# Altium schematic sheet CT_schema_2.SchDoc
size 591 x 347 mm
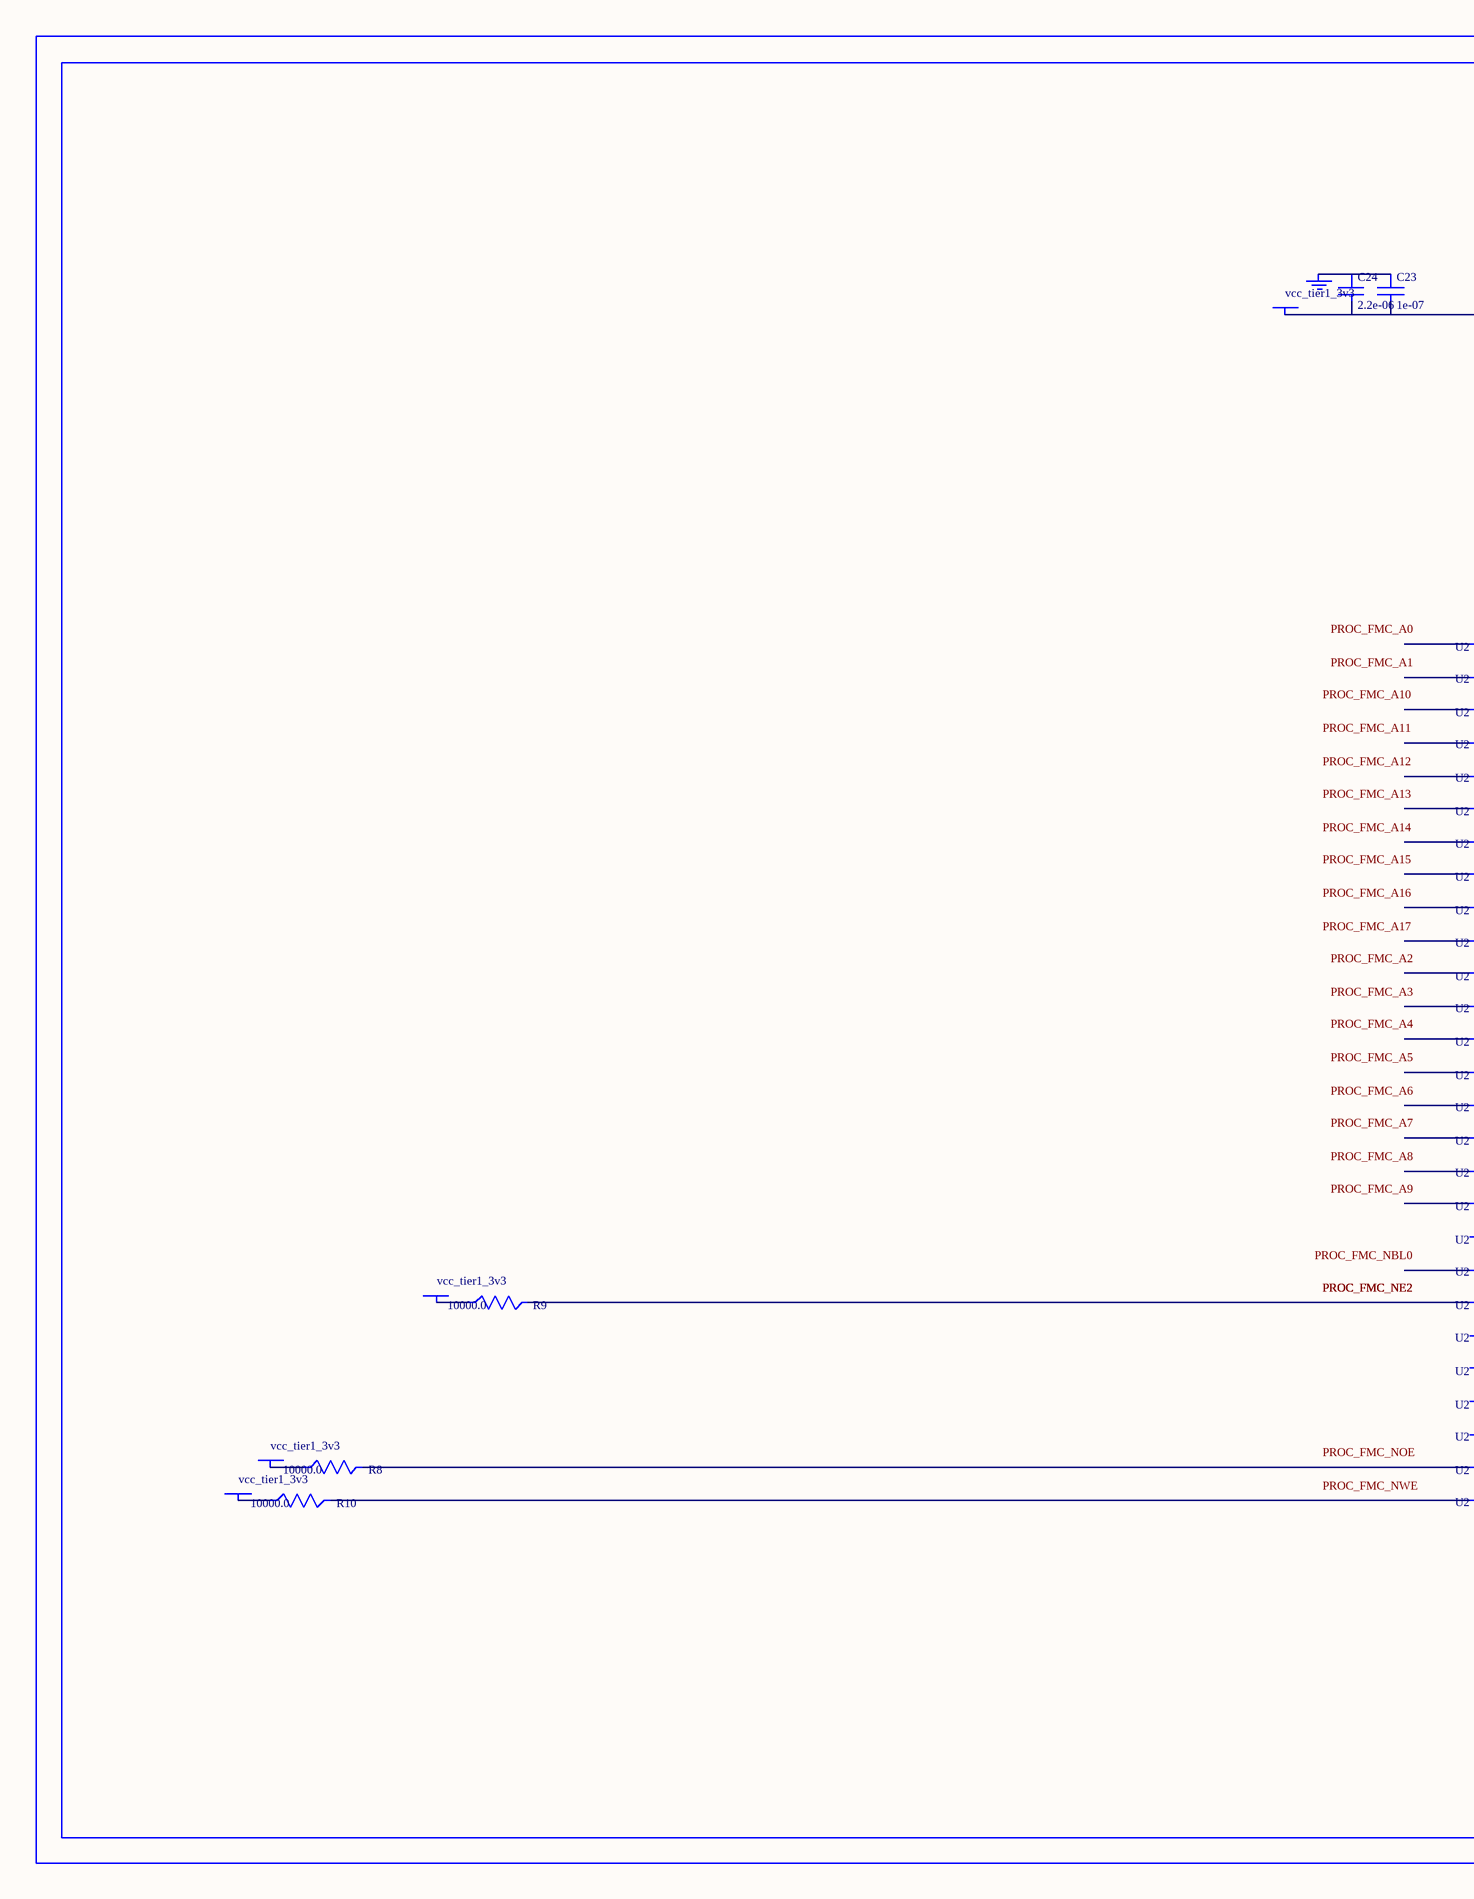
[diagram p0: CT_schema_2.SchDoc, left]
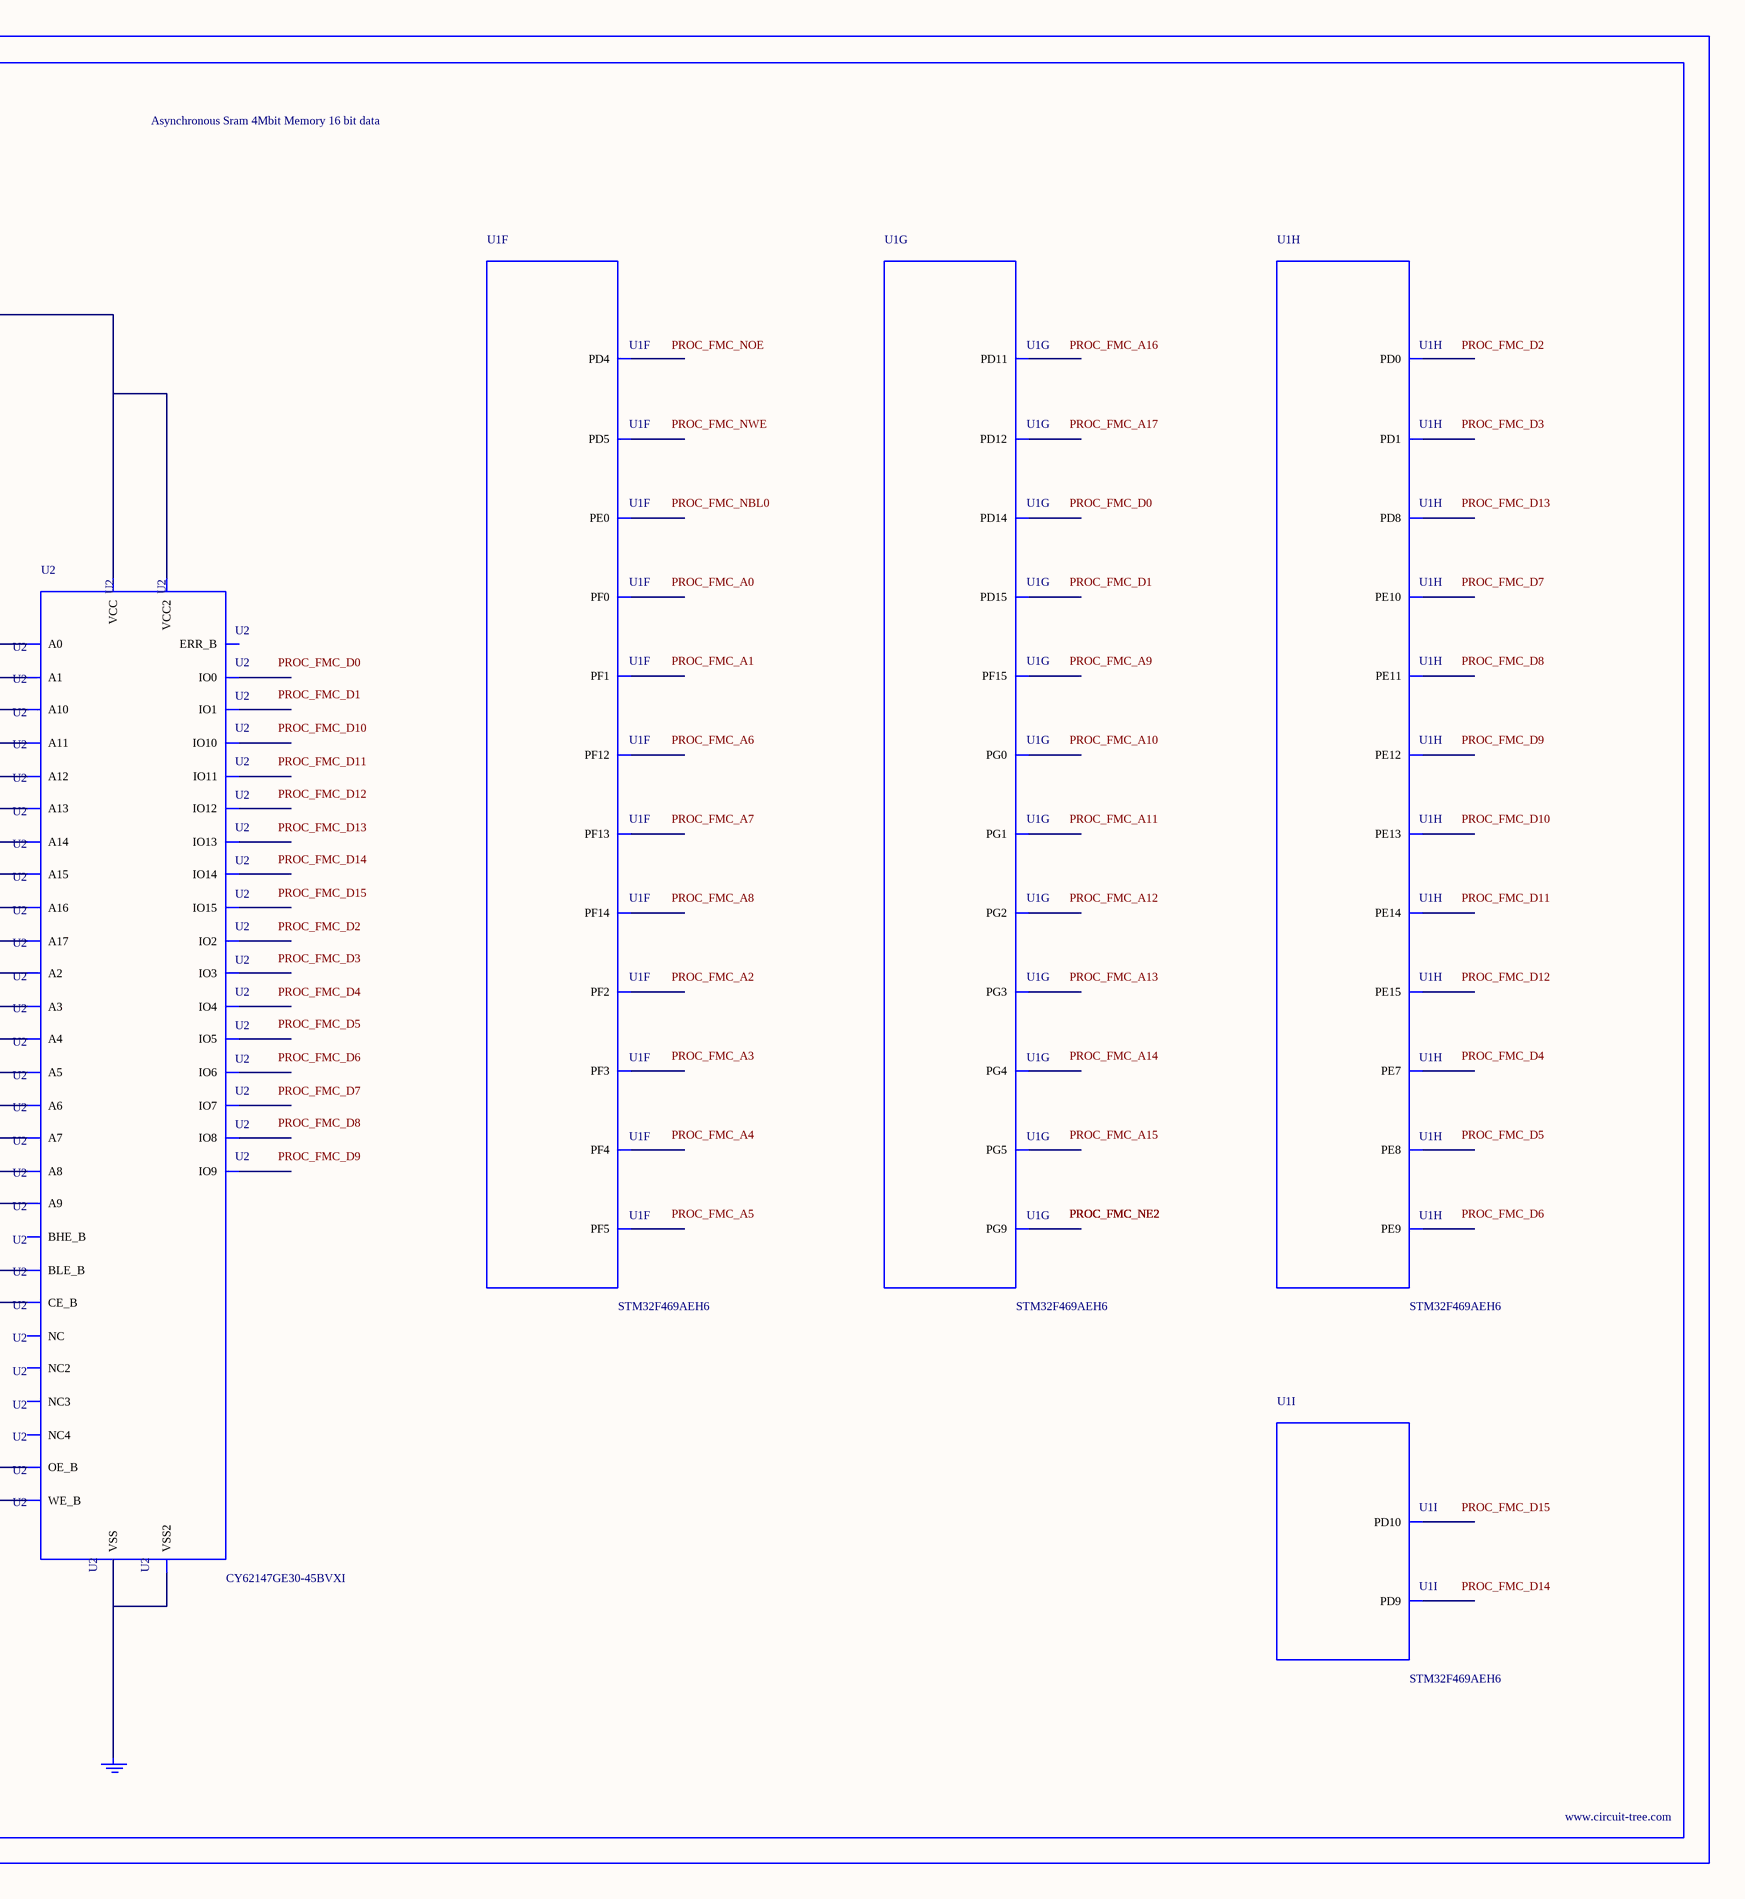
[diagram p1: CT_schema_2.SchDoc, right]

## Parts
BORDER1  (no value)
C23  1e-07  [C0402]
C24  2.2e-06  [C0603]
GND_INSTANCE_1_0  (no value)
GND_INSTANCE_1_1  (no value)
POWER_INSTANCE_1_0  vcc_tier1_3v3
POWER_INSTANCE_1_1  vcc_tier1_3v3
POWER_INSTANCE_1_2  vcc_tier1_3v3
POWER_INSTANCE_1_3  vcc_tier1_3v3
R8  10000.0  [R0603]
R9  10000.0  [R0603]
R10  10000.0  [R0603]
U1  STM32F469AEH6  [UFBGA169]  (parts F,G,H,I of 14)
U2  CY62147GE30-45BVXI  [VFBGA48]

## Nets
NetC23_1: C23.1 C24.1 GND_INSTANCE_1_0.0(GND)
NetC23_2: C23.2 C24.2 POWER_INSTANCE_1_0.0(PWR) U2.D6(VCC) U2.E1(VCC2)
NetGND_INSTANCE_1_1_0: GND_INSTANCE_1_1.0(GND) U2.D1(VSS) U2.E6(VSS2)
NetPOWER_INSTANCE_1_1_0: POWER_INSTANCE_1_1.0(PWR) R8.1
NetPOWER_INSTANCE_1_2_0: POWER_INSTANCE_1_2.0(PWR) R9.1
NetPOWER_INSTANCE_1_3_0: POWER_INSTANCE_1_3.0(PWR) R10.1
NetR8_2: R8.2 U2.A2(OE_B)
NetR9_2: R9.2 U2.B5(CE_B)
NetR10_2: R10.2 U2.G5(WE_B)

Not connected (* = marked no-connect by the designer): U1 A4(PE0) B7(PD5) C6(PD4) C7(PD1) C9(PD0) E6(PG9) E12(PG5) E13(PG4) F3(PF0) F12(PG3) F13(PG2) G3(PF1) G5(PF2) G6(PE8) H3(PF5) H4(PF3) H5(PF14) H6(PE9) H7(PE10) J8(PE13) K7(PE11) K8(PE14) L4(PF4) L7(PE12) L8(PE15) L10(PD8) L11(PD10) L12(PD14) L13(PD15) M4(PF13) M6(PF15) M7(PG1) M10(PD9) M11(PD11) M13(PD12) N5(PF12) N6(PG0) N7(PE7); U2 A1(BLE_B) A3(A0) A4(A1) A5(A2) A6(NC) B1(IO8) B2(BHE_B) B3(A3) B4(A4) B6(IO0) C1(IO9) C2(IO10) C3(A5) C4(A6) C5(IO1) C6(IO2) D2(IO11) D3(A17) D4(A7) D5(IO3) E2(IO12) E3(ERR_B) E4(A16) E5(IO4) F1(IO14) F2(IO13) F3(A14) F4(A15) F5(IO5) F6(IO6) G1(IO15) G2(NC2) G3(A12) G4(A13) G6(IO7) H1(NC3) H2(A8) H3(A9) H4(A10) H5(A11) H6(NC4)

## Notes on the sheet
- Labels drawn without touching a wire or pin: PROC_FMC_A0, PROC_FMC_A1, PROC_FMC_A2, PROC_FMC_A3, PROC_FMC_A4, PROC_FMC_A5, PROC_FMC_A6, PROC_FMC_A7, PROC_FMC_A8, PROC_FMC_A9, PROC_FMC_A10, PROC_FMC_A11, PROC_FMC_A12, PROC_FMC_A13, PROC_FMC_A14, PROC_FMC_A15, PROC_FMC_A16, PROC_FMC_A17, PROC_FMC_D0, PROC_FMC_D1, PROC_FMC_D2, PROC_FMC_D3, PROC_FMC_D4, PROC_FMC_D5, PROC_FMC_D6, PROC_FMC_D7, PROC_FMC_D8, PROC_FMC_D9, PROC_FMC_D10, PROC_FMC_D11, PROC_FMC_D12, PROC_FMC_D13, PROC_FMC_D14, PROC_FMC_D15, PROC_FMC_NBL0, PROC_FMC_NOE, PROC_FMC_NWE

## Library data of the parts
BORDER1 = BORDER_PAGE1
C23 = C0402C104K3RACTU
C24 = C0603C225K8RACTU
GND_INSTANCE_1_0 GND_INSTANCE_1_1 = GND
POWER_INSTANCE_1_0-POWER_INSTANCE_1_3 = PWR
R8-R10 = RC0603JR-0710KL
